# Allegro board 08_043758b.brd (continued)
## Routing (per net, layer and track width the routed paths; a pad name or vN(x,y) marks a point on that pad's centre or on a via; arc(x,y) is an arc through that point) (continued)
IO_L04_34_RX_D7: length 49.6
  TOP w0.102: v2(61.67,100.03) U4.J14 ; U5.J9 v2(36.08,102.36)
  L5_SIG w0.114: v2(61.67,100.03) 61.27,99.63 61.27,96.01 59.06,93.8 51.95,93.8 51.61,94.14 51.4,94.14 51.1,93.83 50.9,93.83 50.75,93.98 50.75,94.18 51.05,94.49 51.05,94.69 50.91,94.84 50.7,94.84 50.27,94.41 50.07,94.41 49.92,94.55 49.92,94.76 50.35,95.19 50.35,95.39 48.26,97.48 47.31,97.48 47.17,97.34 47.17,96.99 47.02,96.85 46.82,96.85 46.67,96.99 46.67,97.34 46.53,97.48 44.74,97.48 44.6,97.63 44.6,98.1 44.45,98.24 44.25,98.24 44.1,98.1 44.1,97.63 43.96,97.48 43.75,97.48 43.61,97.63 43.61,98.1 43.46,98.24 43.26,98.24 43.11,98.1 43.11,97.63 42.97,97.48 42.76,97.48 42.62,97.63 42.62,98.1 42.47,98.24 42.27,98.24 42.12,98.1 42.12,97.63 41.98,97.48 41.77,97.48 41.63,97.63 41.63,98.1 41.48,98.24 41.28,98.24 41.13,98.1 41.13,97.63 40.99,97.48 40.78,97.48 40.64,97.63 40.64,98.1 40.49,98.24 40.29,98.24 40.14,98.1 40.14,97.51 39.6,96.97 38.17,96.97 38.03,97.12 38.03,98.1 37.88,98.24 37.68,98.24 37.53,98.1 37.53,97.12 37.39,96.97 37.09,96.97 36.75,97.32 36.75,101.19 36.08,101.85 v2(36.08,102.36)
IO_L05_34_RX_D8: length 49.1
  TOP w0.102: v2(61.67,99.23) U4.J15 ; U5.K7 v2(35.28,103.16)
  L5_SIG w0.114: v2(61.67,99.23) 61.67,95.77 59.31,93.42 50.42,93.42 50.16,93.68 49.96,93.68 49.72,93.44 49.51,93.44 49.37,93.58 49.37,93.79 49.61,94.03 49.61,94.23 49.33,94.51 49.33,94.71 49.7,95.08 49.7,95.29 49.55,95.43 49.35,95.43 48.98,95.07 48.78,95.07 48.63,95.21 48.63,95.42 49,95.78 49,95.99 48.85,96.13 48.65,96.13 48.28,95.77 48.08,95.77 47.93,95.91 47.93,96.12 48.3,96.48 48.3,96.69 48.15,96.83 47.95,96.83 47.58,96.47 46.43,96.47 46.29,96.61 46.29,96.96 46.14,97.1 45.94,97.1 45.79,96.96 45.79,96.61 45.65,96.47 45.44,96.47 45.3,96.61 45.3,96.96 45.15,97.1 44.95,97.1 44.8,96.96 44.8,96.61 44.66,96.47 44.45,96.47 44.31,96.61 44.31,96.96 44.16,97.1 43.96,97.1 43.81,96.96 43.81,96.61 43.67,96.47 43.46,96.47 43.32,96.61 43.32,96.96 43.17,97.1 42.97,97.1 42.82,96.96 42.82,96.61 42.68,96.47 42.47,96.47 42.33,96.61 42.33,96.96 42.18,97.1 41.98,97.1 41.83,96.96 41.83,96.61 41.69,96.47 41.48,96.47 41.36,96.59 41.36,96.92 41.26,97.02 40.96,97.02 40.86,96.92 40.86,96.63 40.69,96.47 38.74,96.47 38.61,96.59 36.96,96.59 36.5,97.05 36.5,101 35.68,101.82 35.68,102.76 v2(35.28,103.16)
IO_L05_34_RX_D9: length 49
  TOP w0.102: v2(60.87,99.23) U4.K15 ; U5.J8 v2(36.08,103.16)
  L5_SIG w0.114: v2(60.87,99.23) 60.87,96.24 58.8,94.18 52.2,94.18 48.52,97.86 48.18,97.86 48.01,98.04 48.01,99.37 47.85,99.53 47.61,99.53 47.46,99.38 47.46,98.01 47.32,97.86 47.11,97.86 46.97,98.01 46.97,99.38 46.82,99.53 46.62,99.53 46.47,99.38 46.47,98.01 46.33,97.86 46.12,97.86 45.98,98.01 45.98,98.38 45.83,98.53 45.63,98.53 45.48,98.38 45.48,98.01 45.34,97.86 45.13,97.86 44.99,98.01 44.99,98.48 44.84,98.63 44.43,98.63 44.29,98.77 44.29,100.59 44.14,100.73 43.94,100.73 43.79,100.59 43.79,98.77 43.65,98.63 39.77,98.63 39.63,98.48 39.63,97.5 39.48,97.36 39.28,97.36 39.13,97.5 39.13,98.61 38.87,98.88 38.61,98.88 38.36,98.63 37.21,98.63 36.99,98.85 36.99,101.45 36.95,101.48 36.95,101.49 36.49,101.96 36.49,102.76 v2(36.08,103.16)
IO_L06_34_RX_D10: length 49.2
  TOP w0.102: U5.J7 v2(36.89,103.16) ; U4.H11 v2(63.27,102.43)
  L5_SIG w0.114: v2(63.27,102.43) 62.35,101.51 62.35,101.32 62.07,101.04 62.07,100.63 61.87,100.43 60.57,100.43 60.07,99.93 60.07,96.21 58.42,94.56 52.38,94.56 48.39,98.55 48.39,99.51 47.63,100.28 47.63,101.04 47.51,101.16 47.3,101.16 47.15,101.01 47.15,100.04 47,99.9 46.8,99.9 46.65,100.04 46.65,101.01 46.51,101.16 46.3,101.16 46.16,101.01 46.16,100.04 46.01,99.9 45.81,99.9 45.66,100.04 45.66,101.01 45.52,101.16 45.31,101.16 45.17,101.01 45.17,99.15 45.02,99.01 44.82,99.01 44.67,99.15 44.67,101.01 44.53,101.16 43.69,101.16 42.89,100.36 42.89,99.76 42.68,99.56 38.2,99.56 37.29,100.47 37.29,101.5 36.89,101.9 v2(36.89,103.16)
IO_L06_34_RX_D11: length 52.4
  TOP w0.102: U4.J11 v2(61.67,102.43) ; U5.H8 v2(37.69,103.16)
  L5_SIG w0.114: v2(37.69,103.16) 38.09,102.76 38.09,100.55 38.28,100.36 39.49,100.36 39.69,100.56 39.69,101.76 39.89,101.96 40.28,101.96 40.48,101.76 40.48,100.56 40.68,100.36 41.08,100.36 41.28,100.56 41.28,101.76 41.48,101.96 41.89,101.96 42.08,101.76 42.08,101.36 42.28,101.16 42.69,101.16 42.89,101.36 42.89,101.76 43.09,101.96 44.49,101.96 44.89,102.36 45.4,102.36 45.54,102.21 45.54,101.69 45.69,101.55 45.89,101.55 46.04,101.69 46.04,102.21 46.18,102.36 46.44,102.36 46.61,102.18 46.61,101.67 46.74,101.55 47.76,101.55 47.99,101.31 47.99,100.46 48.77,99.68 48.77,98.75 48.94,98.58 49.15,98.58 49.45,98.88 49.66,98.88 49.8,98.74 49.8,98.53 49.5,98.23 49.5,98.03 49.64,97.88 49.85,97.88 50.15,98.18 50.36,98.18 50.5,98.04 50.5,97.83 50.2,97.53 50.2,97.33 50.34,97.18 50.55,97.18 50.85,97.48 51.06,97.48 51.2,97.34 51.2,97.13 50.9,96.83 50.9,96.62 51.04,96.48 51.25,96.48 51.55,96.78 51.76,96.78 51.9,96.64 51.9,96.43 51.6,96.13 51.6,95.92 52.07,95.45 53.11,95.45 53.25,95.6 53.25,95.94 53.4,96.09 53.6,96.09 53.75,95.94 53.75,95.6 53.89,95.45 54.36,95.45 54.5,95.31 54.5,95.09 54.65,94.94 54.85,94.94 55,95.09 55,95.31 55.14,95.45 55.86,95.45 56.01,95.31 56.01,95.09 56.15,94.94 56.36,94.94 56.51,95.09 56.51,95.31 56.65,95.45 56.86,95.45 57,95.31 57,95.09 57.15,94.94 57.35,94.94 57.5,95.09 57.5,95.31 57.64,95.45 58.68,95.45 59.69,96.47 59.69,100.05 60.37,100.73 60.37,101.03 60.57,101.23 61.92,101.23 62.11,101.42 62.11,102.31 61.99,102.43 v2(61.67,102.43)
IO_L07_34_RX_FRAME: length 56
  TOP w0.102: v2(58.47,100.83) U4.N13 ; U5.G8 v2(38.49,103.16)
  L5_SIG w0.114: v2(38.49,103.16) 38.89,103.56 39.85,103.56 39.99,103.71 39.99,104.11 40.14,104.26 40.34,104.26 40.49,104.11 40.49,103.71 40.63,103.56 40.84,103.56 40.98,103.71 40.98,104.11 41.13,104.26 41.33,104.26 41.48,104.11 41.48,103.71 41.62,103.56 41.83,103.56 41.97,103.71 41.97,104.11 42.12,104.26 42.32,104.26 42.47,104.11 42.47,103.71 42.61,103.56 42.82,103.56 43.09,103.83 43.33,103.83 43.6,103.56 43.79,103.56 43.99,103.76 43.99,104.03 44.13,104.18 44.74,104.18 44.89,104.32 44.89,104.53 44.74,104.67 44.13,104.67 43.99,104.82 43.99,105.06 44.18,105.25 45.2,105.25 45.35,105.11 45.35,104.23 45.49,104.09 45.7,104.09 45.84,104.23 45.84,105.56 45.99,105.71 46.19,105.71 46.34,105.56 46.34,104.23 46.48,104.09 46.69,104.09 46.83,104.23 46.83,105.56 46.98,105.71 47.18,105.71 47.33,105.56 47.33,104.23 47.47,104.09 47.68,104.09 47.82,104.23 47.82,105.16 47.97,105.3 48.88,105.3 49.03,105.16 49.03,104.95 48.88,104.81 48.46,104.81 48.32,104.66 48.32,104.46 48.46,104.31 49.38,104.31 49.53,104.17 49.53,103.96 49.38,103.82 48.46,103.82 48.32,103.67 48.32,103.4 48.82,102.9 49.02,102.9 49.44,103.32 49.64,103.32 49.79,103.17 49.79,102.97 49.37,102.55 49.37,102.34 49.52,102.2 49.72,102.2 50.14,102.62 50.34,102.62 51.95,101.01 51.95,98.88 52.19,98.64 52.4,98.64 53.1,99.34 53.31,99.34 53.45,99.2 53.45,98.99 52.75,98.29 52.75,98.08 52.89,97.94 53.1,97.94 53.4,98.24 53.61,98.24 53.75,98.1 53.75,97.89 53.45,97.58 53.45,97.38 53.59,97.23 53.8,97.23 54.1,97.54 54.31,97.54 54.45,97.4 54.45,97.19 54.15,96.88 54.15,96.68 54.67,96.16 58.4,96.16 58.9,96.66 58.9,97.36 58.47,97.78 v2(58.47,100.83)
IO_L08_34_CTRL_OUT0: length 30.4
  TOP w0.102: v2(55.67,97.93) 56.63,96.96 58.51,96.96 60.47,98.92 U4.L15 ; U5.D4 v2(40.88,106.36)
  L5_SIG w0.114: v2(55.67,97.93) 55.67,99.83 55.37,100.13 54.77,100.13 54.49,100.41 54.49,100.91 51.06,104.34 51.06,105.99 49.53,107.52 44.45,107.52 43.61,108.36 41.49,108.36 41.29,108.16 41.29,106.76 v2(40.88,106.36)
IO_L08_34_CTRL_OUT1: length 31.1
  TOP w0.102: U5.E4 v2(40.08,106.36) ; v2(57.27,97.93) 57.64,97.55 58.3,97.55 59.67,98.92 U4.M15
  L5_SIG w0.114: v2(40.08,106.36) 40.49,106.76 40.49,108.96 40.69,109.17 43.69,109.17 44.96,107.9 49.66,107.9 51.44,106.12 51.44,105.36 52.16,104.63 52.16,103.73 53.87,102.03 54.27,102.03 55.37,100.93 56.77,100.93 57.27,100.43 v2(57.27,97.93)
IO_L09_34_TX_FRAME: length 28.7
  TOP w0.102: v2(38.48,102.36) U5.G9 ; v2(60.87,100.03) U4.L14
  L6_SIG w0.114: v2(38.48,102.36) 38.88,101.96 38.88,98.86 39.68,98.06 39.92,98.06 40.88,97.1 57.94,97.1 v2(60.87,100.03)
IO_L10_34_EN_AGC: length 35.1
  TOP w0.102: v2(56.47,97.93) 57.14,97.25 58.4,97.25 60,98.85 60,100.76 U4.L13 ; U5.G5 v2(37.68,105.56)
  L5_SIG w0.114: v2(37.68,105.56) 38.09,105.16 38.09,104.56 38.29,104.36 39.09,104.36 40.69,105.96 41.99,105.96 42.19,106.16 42.19,106.77 42.55,107.13 49.41,107.13 50.68,105.86 50.68,104.22 53.67,101.23 53.67,100.23 55.17,98.73 55.17,97.72 55.44,97.45 55.99,97.45 v2(56.47,97.93)
IO_L11_34_ENABLE: length 30.7
  TOP w0.102: U5.G6 v2(37.68,104.76) ; U4.K12 v2(60.87,101.63)
  L6_SIG w0.114: v2(37.68,104.76) 38.09,105.16 38.09,105.76 38.29,105.96 38.69,105.96 39.69,106.96 39.69,107.36 39.89,107.56 51.94,107.56 54.07,105.43 55.17,105.43 55.77,104.83 56.17,104.83 56.37,105.03 56.37,105.43 56.66,105.73 57.37,105.73 57.87,105.23 58.67,105.23 59.67,104.23 59.67,102.23 59.87,102.03 60.47,102.03 v2(60.87,101.63)
IO_L11_34_TXNRX: length 32.7
  TOP w0.102: U5.H4 v2(36.89,106.36) ; U4.K11 v2(60.87,102.43)
  L6_SIG w0.114: v2(60.87,102.43) 60.47,102.83 60.47,105.83 60.27,106.03 54.47,106.03 50.7,109.8 38.02,109.8 37.29,109.06 37.29,106.76 v2(36.89,106.36)
IO_L12_MRCC_34_DATA_CLK: length 55.5
  TOP w0.102: U5.G11 v2(38.49,100.76) ; U4.L12 v2(60.07,101.63)
  L5_SIG w0.114: v2(60.07,101.63) 60.07,100.93 59.31,100.17 59.31,96.57 58.57,95.83 54.49,95.83 53.09,97.23 52.88,97.23 52.45,96.8 52.25,96.8 52.1,96.95 52.1,97.15 52.53,97.58 52.53,97.79 52.39,97.93 52.18,97.93 51.75,97.5 51.55,97.5 51.4,97.65 51.4,97.85 51.83,98.28 51.83,98.49 51.69,98.63 51.48,98.63 51.05,98.2 50.85,98.2 50.7,98.35 50.7,98.55 51.51,99.36 51.51,99.57 51.37,99.71 51.16,99.71 50.35,98.9 50.15,98.9 50,99.05 50,99.25 50.94,100.19 50.94,100.4 50.79,100.54 50.59,100.54 49.52,99.48 49.32,99.48 49.17,99.62 49.17,99.83 50.62,101.27 50.62,101.48 50.43,101.67 50.22,101.67 48.86,100.3 48.65,100.3 48.51,100.44 48.51,100.65 49.28,101.42 49.28,101.8 49.04,102.04 48.83,102.04 48.47,101.68 48.26,101.68 48.12,101.82 48.12,102.03 48.48,102.39 48.48,102.6 48.34,102.74 48.13,102.74 47.51,102.12 47.31,102.12 47.16,102.27 47.16,102.47 47.78,103.09 47.78,103.42 47.5,103.71 46.99,103.71 46.85,103.56 46.85,102.9 46.7,102.76 46.46,102.76 46.32,102.9 46.32,103.56 46.17,103.71 45.97,103.71 45.82,103.56 45.82,102.9 45.68,102.76 45.47,102.76 45.33,102.9 45.33,103.56 45.18,103.71 44.97,103.71 44.83,103.56 44.83,102.78 44.68,102.63 44.48,102.63 44.33,102.78 44.33,103.05 44.19,103.2 43.98,103.2 43.84,103.05 43.84,102.9 43.69,102.76 39.09,102.76 38.89,102.57 38.89,101.17 v2(38.49,100.76)
IO_L13_34_CTRL_OUT2: length 29.4
  TOP w0.102: U5.E5 v2(39.28,105.56) ; U4.N11 v2(58.47,102.43)
  L5_SIG w0.114: v2(58.47,102.43) 57.17,102.43 56.37,101.62 55.67,101.62 54.67,102.63 54.67,102.93 53.47,104.13 53.47,104.73 53.06,105.13 52.76,105.13 52.07,105.82 52.07,106.5 49.95,108.63 45.25,108.63 43.95,109.93 40.52,109.93 39.75,109.17 39.75,108.63 39.48,108.36 38.98,108.36 38.79,108.16 38.79,107.06 39.28,106.56 v2(39.28,105.56)
IO_L13_34_CTRL_OUT3: length 30.3
  TOP w0.102: U5.E6 v2(40.08,104.76) ; U4.N12 v2(58.47,101.63)
  L5_SIG w0.114: v2(40.08,104.76) 40.48,105.16 42.09,105.16 42.59,105.66 42.59,106.41 42.93,106.75 48.14,106.75 49.91,104.98 49.91,103.98 50.36,103.53 50.86,103.53 53.37,101.03 53.37,99.98 54.77,98.58 54.77,97.62 55.32,97.07 57.12,97.07 57.67,97.62 57.67,100.83 v2(58.47,101.63)
IO_L15_34_TX_D0: length 23.4
  TOP w0.102: U4.P15 58.07,99.33 57.69,98.95 54.05,98.95 v2(53.85,98.75) ; U5.E12 39.76,99.48 39.76,99.46 v2(40.07,99.15)
  L6_SIG w0.114: v2(53.85,98.75) 54.49,98.75 54.74,98.5 54.74,98.24 54.36,97.86 52.03,97.86 51.77,98.12 51.32,98.12 51.06,97.86 50.69,97.86 50.43,98.12 49.98,98.12 49.73,97.86 49.36,97.86 49.1,98.12 48.65,98.12 48.39,97.86 48.02,97.86 47.76,98.12 47.31,98.12 47.06,97.86 46.68,97.86 46.42,98.12 45.97,98.12 45.72,97.86 45.34,97.86 45.09,98.12 44.64,98.12 44.38,97.86 40.98,97.86 40.07,98.77 v2(40.07,99.15)
IO_L15_34_TX_D1: length 23.2
  TOP w0.102: v2(54.07,100.63) 54.46,101.03 56.77,101.03 56.97,101.22 57.26,101.22 U4.R13 ; U5.D11 v2(40.89,99.96)
  L6_SIG w0.114: v2(54.07,100.63) 53.37,100.63 52.97,100.23 52.97,99.64 52.58,99.26 50.51,99.26 50.37,99.41 50.37,100 50.22,100.15 50.01,100.15 49.87,100 49.87,99.41 49.72,99.26 49.52,99.26 49.37,99.41 49.37,100 49.23,100.15 49.02,100.15 48.88,100 48.88,99.41 48.73,99.26 48.53,99.26 48.38,99.41 48.38,100 48.24,100.15 48.03,100.15 47.89,100 47.89,99.41 47.74,99.26 46.99,99.26 46.23,100.02 43.95,100.02 43.48,99.56 41.49,99.56 41.28,99.76 41.28,99.89 41.21,99.96 v2(40.89,99.96)
IO_L16_34_TX_D2: length 22.7
  TOP w0.102: U5.E11 40.07,99.97 40.07,99.96 v2(40.08,99.95) ; v2(54.97,99.63) U4.R15
  L6_SIG w0.114: v2(40.08,99.95) 40.08,99.66 40.18,99.56 40.28,99.56 40.48,99.36 40.48,98.86 41.1,98.24 44.2,98.24 44.43,98.48 44.43,99.01 44.58,99.16 44.78,99.16 44.93,99.01 44.93,98.7 45.13,98.5 52.96,98.5 53.95,99.49 54.31,99.49 54.72,99.07 55.61,99.07 55.81,99.27 55.81,99.45 55.63,99.63 v2(54.97,99.63)
IO_L16_34_TX_D3: length 23.6
  TOP w0.102: U5.D10 v2(40.88,100.76) ; v2(51.36,100.63) 52.36,101.63 56.27,101.63 57.07,102.43 57.66,102.43 U4.P11
  L6_SIG w0.114: v2(51.36,100.63) 51.79,100.63 51.95,100.78 51.95,101.04 51.82,101.17 50.03,101.17 49.8,100.93 49.59,100.93 49.45,101.07 49.45,101.32 49.3,101.46 49.1,101.46 48.95,101.32 48.95,101.07 48.81,100.93 48.6,100.93 48.46,101.07 48.46,101.32 48.31,101.46 48.11,101.46 47.96,101.32 47.96,101.07 47.82,100.93 47.61,100.93 47.47,101.07 47.47,101.32 47.32,101.46 47.12,101.46 46.97,101.32 46.97,100.95 46.83,100.8 46.62,100.8 46.48,100.95 46.48,101.32 46.33,101.46 46.09,101.46 45.49,100.86 44.49,100.86 44.19,101.16 41.28,101.16 v2(40.88,100.76)
IO_L17_34_TX_D4: length 23.2
  TOP w0.102: U4.R11 56.87,102.83 v2(56.07,102.03) ; U5.E10 v2(40.08,100.76)
  L6_SIG w0.114: v2(56.07,102.03) 56.5,101.6 56.5,101.16 55.5,100.16 53.61,100.16 53.39,99.95 53.39,99.44 52.84,98.88 46.77,98.88 46.13,99.51 44.24,99.51 43.95,99.22 43.95,98.92 43.69,98.66 41.49,98.66 41.28,98.86 41.28,99.36 41.09,99.56 40.69,99.56 40.48,99.76 40.48,100.16 40.28,100.36 40.16,100.36 40.08,100.43 v2(40.08,100.76)
IO_L17_34_TX_D5: length 22.7
  TOP w0.102: U5.D9 v2(40.88,101.56) ; v2(52.37,100.63) 53.06,101.33 56.54,101.33 56.67,101.45 56.69,101.45 U4.R12
  L6_SIG w0.114: v2(40.88,101.56) 41.29,101.96 43.89,101.96 44.59,101.26 45.29,101.26 45.89,101.86 49.6,101.86 49.91,101.55 52.14,101.55 52.47,101.88 52.47,102.19 52.62,102.33 53.47,102.33 53.85,101.94 53.85,101.62 52.86,100.63 v2(52.37,100.63)
IO_L18_34_TX_D6: length 22.9
  TOP w0.102: v2(52.37,99.83) 52.94,99.25 57.49,99.25 57.67,99.43 57.67,100.03 U4.P14 ; U5.E9 v2(40.08,101.56)
  L6_SIG w0.114: v2(52.37,99.83) 51.75,99.83 51.57,99.64 51.06,99.64 50.8,99.9 50.8,100.55 50.59,100.76 50.27,100.76 50.04,100.53 47.63,100.53 47.41,100.31 47.41,99.89 47.29,99.76 47.02,99.76 46.89,99.89 46.89,100.26 46.75,100.4 43.74,100.4 43.39,100.76 43.14,100.76 43,100.61 43,100.5 42.85,100.36 40.73,100.36 40.48,100.6 40.48,101.16 v2(40.08,101.56)
IO_L18_34_TX_D7: length 22.7
  TOP w0.102: U4.P13 57.66,100.82 56.96,100.82 56.77,100.63 55.17,100.63 55.17,100.63 v2(54.96,100.63) ; U5.D8 v2(40.88,102.36)
  L6_SIG w0.114: v2(40.88,102.36) 41.29,102.76 43.69,102.76 44.19,102.26 49.85,102.26 50,102.4 50,102.62 50.14,102.76 50.48,102.76 50.62,102.62 50.62,102.4 50.77,102.26 50.97,102.26 51.12,102.4 51.12,102.62 51.26,102.76 53.59,102.76 54.3,102.05 54.87,102.05 55.14,102.33 55.47,102.33 55.67,102.13 55.67,100.83 55.46,100.63 v2(54.96,100.63)
IO_L19_34_TX_D8: length 22.6
  TOP w0.102: U5.E8 v2(40.08,102.36) ; v2(55.96,103.63) 56.36,104.03 58.47,104.03 U4.N9
  L6_SIG w0.114: v2(55.96,103.63) 53.47,103.63 53.4,103.56 47.39,103.56 47.25,103.71 46.23,103.71 45.99,103.46 45.99,103.21 45.85,103.06 45.64,103.06 45.5,103.21 45.5,103.52 45.35,103.66 45.14,103.66 45,103.52 45,103.21 44.85,103.06 44.65,103.06 44.5,103.21 44.5,103.65 44.29,103.86 40.99,103.86 40.48,103.36 40.48,102.76 v2(40.08,102.36)
IO_L19_34_TX_D9: length 23.4
  TOP w0.102: U4.M9 59.27,104.83 v2(58.47,104.83) ; U5.D7 v2(40.88,103.16)
  L6_SIG w0.114: v2(58.47,104.83) 58.47,104.43 58.07,104.03 56.57,104.03 56.37,103.83 56.37,103.43 56.17,103.24 53.97,103.24 53.9,103.16 49.89,103.16 49.39,102.66 49.08,102.66 48.93,102.81 48.93,103.02 48.79,103.16 48.58,103.16 48.44,103.02 48.44,102.81 48.29,102.66 48.09,102.66 47.94,102.81 47.94,103.02 47.8,103.16 47.59,103.16 47.45,103.02 47.45,102.81 47.3,102.66 47.1,102.66 46.95,102.81 46.95,103.02 46.81,103.16 46.6,103.16 46.46,103.02 46.46,102.81 46.31,102.66 44.39,102.66 43.49,103.56 41.29,103.56 40.89,103.16 v2(40.88,103.16)
IO_L20_34_TX_D10: length 22.4
  TOP w0.102: v2(56.76,105.22) 56.77,105.23 U4.R8 ; U5.F8 v2(39.28,102.36)
  L6_SIG w0.114: v2(56.76,105.22) 56.67,104.93 56.37,104.63 56.37,104.23 56.16,104.03 53.91,104.03 53.6,104.34 53.6,104.9 53.39,105.1 44.58,105.1 44.1,105.59 42.71,105.59 42.48,105.36 42.48,104.91 41.93,104.36 40.68,104.36 40.22,103.9 40.02,103.9 39.68,103.56 39.68,102.76 39.29,102.36 v2(39.28,102.36)
IO_L20_34_TX_D11: length 22.8
  TOP w0.102: U4.R7 56.86,106.03 56.77,105.93 54.57,105.93 v2(53.07,104.43) ; U5.E7 v2(40.08,103.16)
  L6_SIG w0.114: v2(40.08,103.16) 40.08,103.56 40.19,103.66 40.39,103.66 40.85,104.12 42.33,104.12 42.94,104.73 44.06,104.73 44.68,104.12 45.26,104.12 45.41,104.26 45.41,104.42 45.55,104.56 45.76,104.56 45.9,104.42 45.9,104.26 46.05,104.12 46.25,104.12 46.4,104.26 46.4,104.42 46.54,104.56 46.75,104.56 46.89,104.42 46.89,104.26 47.04,104.12 47.24,104.12 47.39,104.26 47.39,104.42 47.53,104.56 47.74,104.56 47.88,104.42 47.88,104.14 48.03,103.99 48.23,103.99 48.38,104.14 48.38,104.54 48.52,104.69 48.73,104.69 48.87,104.54 48.87,104.12 49.03,103.96 52.94,103.96 53.07,104.09 v2(53.07,104.43)
IO_L21_34_CTRL_OUT4: length 32.1
  TOP w0.102: U4.M10 v2(59.27,103.23) ; U5.F6 v2(38.49,104.76)
  L5_SIG w0.114: v2(59.27,103.23) 59.67,102.83 59.67,102.22 59.47,102.02 57.47,102.02 56.8,101.36 55.45,101.36 54.47,102.33 54.07,102.33 52.56,103.83 52.56,104.73 51.8,105.49 51.8,106.26 49.81,108.26 45.11,108.26 43.82,109.55 40.64,109.55 40.14,109.04 40.14,108.61 39.68,108.16 39.68,105.36 39.49,105.16 38.89,105.16 v2(38.49,104.76)
IO_L21_34_CTRL_OUT5: length 30.6
  TOP w0.102: U5.F5 v2(38.49,105.55) ; U4.M11 v2(59.27,102.43)
  L5_SIG w0.114: v2(59.27,102.43) 58.87,102.83 56.88,102.83 56.47,102.43 55.9,102.43 55.57,102.76 55.57,103.03 54.87,103.73 54.23,103.73 53.77,104.19 53.77,105.63 49.09,110.31 40.26,110.31 38.49,108.53 38.49,106.96 38.88,106.56 38.88,105.95 v2(38.49,105.55)
IO_L22_34_CTRL_OUT6: length 32.3
  TOP w0.102: U5.F4 v2(38.48,106.36) ; v2(58.47,106.43) U4.N7
  L5_SIG w0.114: v2(58.47,106.43) 57.3,105.26 57.3,104.36 56.97,104.03 55.8,104.03 55.57,104.26 55.57,104.83 49.33,111.07 39.88,111.07 38.23,109.42 37.72,109.42 37.28,108.98 37.28,106.06 37.38,105.96 38.08,105.96 v2(38.48,106.36)
IO_L22_34_CTRL_OUT7: length 30.1
  TOP w0.102: v2(58.47,105.63) U4.N8 ; U5.G4 v2(37.68,106.36)
  L5_SIG w0.114: v2(37.68,106.36) 38.09,106.76 38.09,108.64 40.14,110.69 49.21,110.69 54.77,105.13 54.77,104.23 55.77,103.23 57.27,103.23 58.07,104.03 58.07,105.23 v2(58.47,105.63)
IO_L23_35_SPI_CLK: length 70.5
  TOP w0.102: U5.J5 v2(36.09,105.56) ; U4.E11 v2(65.67,102.43)
  L5_SIG w0.114: v2(65.67,102.43) 66.07,102.83 67.47,102.83 67.67,102.62 67.67,100.13 67.87,99.93 67.87,98.33 67.37,97.83 67.37,90.3 66.46,89.39 63.01,89.39 62.72,89.1 51.31,89.1 50.68,88.47 43.82,88.47 43.06,89.23 36.71,89.23 30.45,95.49 30.45,102.5 33.1,105.16 35.69,105.16 v2(36.09,105.56)
IO_L23_35_SPI_ENB: length 66.4
  TOP w0.102: U5.K6 v2(35.28,104.76) ; U4.E12 v2(65.67,101.63)
  L5_SIG w0.114: v2(65.67,101.63) 66.07,102.03 66.67,102.03 66.87,101.83 66.87,100.32 67.57,99.62 67.57,98.53 67.07,98.03 67.07,90.64 66.21,89.77 62.63,89.77 62.34,89.48 51.06,89.48 50.42,88.85 46.1,88.85 45.47,89.48 36.96,89.48 30.75,95.7 30.75,102.38 32.72,104.36 34.88,104.36 v2(35.28,104.76)
IO_L24_35_SPI_DI: length 64.2
  TOP w0.102: U5.J4 v2(36.08,106.36) ; U4.E13 v2(65.67,100.83)
  L5_SIG w0.114: v2(65.67,100.83) 65.77,100.53 66.47,99.82 66.47,91.21 65.8,90.53 62.12,90.53 61.83,90.24 37.21,90.24 31.34,96.12 31.34,102.12 31.53,102.32 31.74,102.32 31.96,102.09 32.17,102.09 32.31,102.23 32.31,102.44 32.09,102.67 32.09,102.87 32.77,103.56 35.78,103.56 36.48,104.26 U5.J4 v2(36.08,106.36)
IO_L24_35_SPI_DO: length 62.7
  TOP w0.102: U4.F12 v2(64.87,101.63) ; U5.L6 v2(34.48,103.96)
  L5_SIG w0.114: v2(34.48,103.96) 32.75,103.96 31.05,102.25 31.05,95.9 37.09,89.86 62.08,89.86 62.37,90.15 66.08,90.15 66.77,90.85 66.77,98.23 67.27,98.73 67.27,99.42 66.07,100.63 66.07,101.13 65.97,101.23 65.53,101.23 65.13,101.63 v2(64.87,101.63)
JTAG_TCK: length 49.9
  TOP w0.102: P1.4 71.38,80.59 68.84,80.59 TCK.1 ; v1(78.88,103.71) 78.37,104.21 72.59,104.21 72.08,104.72 70.09,104.72 69.98,104.83 64.07,104.83 U4.G9
  L5_SIG w0.114: v1(75.7,83) 75.7,83.64 77.36,85.3 77.36,91.02 78.25,91.91 78.25,97.45 77.28,98.42 77.28,100.15 78.25,101.12 78.25,103.07 v1(78.88,103.71)
  BOTTOM w0.102: v1(75.7,83) 75.06,82.37 73.28,82.37 72.65,81.73 P1.4
JTAG_TDI: length 43.7
  TOP w0.102: U4.L7 v2(60.07,106.43) ; P1.8 75.95,80.08 77.6,80.08 78.36,79.32 78.36,78.69 TDI.1
  L5_SIG w0.114: v2(60.07,106.43) 60.07,106.43 60.46,106.03 62.67,106.03 63.97,104.73 67.81,104.73 69.98,102.57 69.98,95.71 71.12,94.56 71.12,89.74 72.39,88.47 72.39,82.12 P1.8
JTAG_TDO: length 42.9
  TOP w0.102: P1.6 75.19,80.59 77.73,80.59 78.36,79.96 TDO.1 ; U4.L8 v2(60.07,105.63)
  L5_SIG w0.114: P1.6 71.89,81.35 71.89,88.34 70.74,89.48 70.74,94.31 69.22,95.83 69.22,100.92 68.77,101.37 68.77,101.85 68.47,102.15 68.47,103.63 67.68,104.43 63.87,104.43 63.07,105.23 60.46,105.23 60.07,105.63 v2(60.07,105.63)
JTAG_TMS: length 38.5
  TOP w0.102: TMS.1 70.11,79.32 P1.2 ; U4.L9 v2(60.07,104.83)
  L5_SIG w0.114: v2(60.07,104.83) 61.27,103.63 67.67,103.63 68.07,103.23 68.07,102.19 68.46,101.81 68.46,101.1 68.84,100.72 68.84,95.58 70.36,94.05 70.36,89.23 71.38,88.21 P1.2
PG_1P0V: length 21.6
  TOP w0.305: U3.16 101.11,93.43 v1(101.48,93.8)
  BOTTOM w0.203: R86.1 97.67,110.18 98.3,109.55 98.3,106.3 102.24,102.36 102.24,94.56 v1(101.48,93.8)
  BOTTOM w0.305: R6.2 v1(101.48,93.8)
PG_1P3V: length 94.8
  TOP w0.127: U1.5 30.82,82.79 30.99,82.62 v1(30.99,82.24) ; v2(67.27,104.03) 66.87,104.43 U4.C9 ; U7.5 v1(51.69,82.12) ; U12.4 v1(59.82,86.29)
  L5_SIG w0.127: v1(79.01,83.04) 79.01,97.52 79.78,98.29 79.78,100.02 79.01,100.79 79.01,101.33 80.03,102.35 v1(80.03,102.73)
  L6_SIG w0.127: v1(79.01,83.04) 78.12,82.15 72.28,82.15 67.45,86.98 64.41,86.98 63.72,86.29 v1(59.82,86.29) ; v1(80.03,102.73) 80.03,103.68 79.49,104.21 78.49,104.21 78.3,104.03 v2(67.27,104.03)
  BOTTOM w0.127: v1(59.82,86.29) 56.53,83 55.88,83 PG_1P3V.1 54.99,82.12 v1(51.69,82.12) 46.36,82.12 45.22,80.97 38.54,80.97 37.74,81.77 31.46,81.77 v1(30.99,82.24) ; R13.2 81.49,103.9 C47.1 80.06,103.9 R15.1 80.03,103.32 v1(80.03,102.73)
PG_1P8V: length 12
  TOP w0.203: v2(100.33,119.38) 100.33,119.33 100.34,119.32 U6.13 ; v2(100.96,112.58) 100.84,112.93 U6.29
  L5_SIG w0.305: v2(100.33,119.38) 100.33,119.33 100.84,118.82 102.11,118.82 102.75,118.18 102.75,114.75 100.96,112.96 v2(100.96,112.58)
  BOTTOM w0.305: v2(100.96,112.58) 100.96,111.83 R59.1
PG_1P35V: length 124.9
  TOP w0.127: U7.4 50.76,81.52 51.06,81.23 v1(52.58,81.23) ; v1(30.23,81.23) 29.59,81.87 U1.4
  TOP w0.203: v2(100.97,120.09) 100.84,119.7 U6.12
  L5_SIG w0.127: v2(100.97,120.09) 97.01,120.09 94.12,117.2 94.12,110.47 88.41,104.76 88.41,99.68 87.9,99.17 87.9,93.07 86.25,91.42 86.25,90.15 84.73,88.63 84.73,83.75 v1(85.47,83)
  L6_SIG w0.127: v1(52.58,81.23) 52.58,81.99 53.51,82.91 56.53,82.91 59.2,85.58 65.17,85.58 65.68,86.09 67.58,86.09 72.03,81.64 78.78,81.64 80.52,83.39 85.09,83.39 v1(85.47,83)
  BOTTOM w0.127: v1(30.23,81.23) 37.27,81.23 38.24,80.25 45.74,80.25 46.72,81.23 v1(52.58,81.23) ; v2(100.97,120.09) 100.97,119.33 100.46,118.82 93.98,118.82 92.08,116.91 R50.1
PL_GPIO0: length 50.1
  TOP w0.127: U4.K13 v2(60.87,100.83)
  L6_SIG w0.127: v2(60.87,100.83) 61.07,100.83 61.47,101.23 61.97,101.23 62.77,102.03 65.07,102.03 65.27,101.83 65.27,101.43 65.47,101.23 65.87,101.23 66.07,101.03 66.07,99.92 66.37,99.62 66.37,98.72 67.07,98.02 67.07,90.62 73.56,84.13 90.06,84.13 91.7,82.5 91.7,79.96 L10P.1
PL_GPIO1: length 55.5
  TOP w0.102: U4.M12 v2(59.27,101.63)
  L6_SIG w0.127: L12N.1 94.24,79.96 94.24,81.86 91.19,84.91 77.35,84.91 76.27,85.99 72.9,85.99 67.87,91.02 67.87,99.22 66.87,100.22 66.87,101.03 66.67,101.23 66.27,101.23 66.07,101.43 66.07,102.63 65.87,102.83 61.47,102.83 61.27,102.63 61.27,101.43 61.07,101.23 59.57,101.23 59.27,101.53 v2(59.27,101.63)
PL_GPIO2: length 52
  TOP w0.127: U4.R10 v2(56.79,103.63)
  L6_SIG w0.127: v2(56.79,103.63) 56.79,103.41 58.07,102.13 58.07,100.7 58.33,100.43 62.61,100.43 62.89,100.71 62.89,101.05 63.07,101.23 65.07,101.23 65.27,101.03 65.27,99.72 65.47,99.52 65.87,99.52 66.07,99.32 66.07,98.2 66.67,97.6 66.67,90.42 73.36,83.73 89.83,83.73 90.43,83.13 L24N.1
PS-SRST#: length 33.3
  TOP w0.127: v1(79.78,101.03) 78.58,101.03 78.38,100.83 72.77,100.83 72.28,101.32 R74.2 70.49,102.18 70.24,102.43 68.07,102.43 U4.B11 ; v2(84.08,116.26) U13.A4
  L5_SIG w0.127: v1(79.78,101.03) 80.78,102.03 81.98,102.03 84.08,104.12 v2(84.08,116.26)
PS_GPIO0: length 54.7
  TOP w0.102: U4.D8 v2(65.67,105.63)
  L5_SIG w0.127: v2(65.67,105.63) 66.07,106.03 66.67,106.03 67.17,106.53 67.77,106.53 68.57,107.33 71.27,107.33 v1(72.07,108.13)
  L6_SIG w0.127: MIO0.1 100.59,82.75 92.89,90.45 92.89,94.32 v1(92.49,94.72)
  BOTTOM w0.127: v1(92.49,94.72) 92.49,95.29 92.35,95.44 92.35,98.66 91.46,99.55 90.31,99.55 89.68,100.19 89.68,102.22 85.29,106.61 75.52,106.61 75.3,106.83 72.57,106.83 72.07,107.33 v1(72.07,108.13)
PS_GPIO1: length 55.8
  TOP w0.127: U4.B10 68.07,103.23 71.77,103.23 72.17,102.83 77.13,102.83 78.38,101.58 80.32,101.58 v1(80.88,101.03)
  L5_SIG w0.127: v1(80.88,101.03) 81.98,99.92 81.98,99.02 80.98,98.02 80.98,85.39 84.73,81.64 87.98,81.64 89.16,80.46 89.16,77.92 89.79,77.29 99.19,77.29 MIO10.1
PS_GPIO2: length 52.9
  TOP w0.127: U4.D6 v2(65.67,106.43)
  L5_SIG w0.127: v2(65.67,106.43) 66.07,106.83 67.47,106.83 68.27,107.63 70.77,107.63 v1(71.27,108.13)
  L6_SIG w0.127: MIO11.1 98.05,84.65 91.89,90.81 v1(91.89,94.12)
  BOTTOM w0.127: v1(71.27,108.13) 71.27,107.63 72.37,106.53 75.18,106.53 75.39,106.31 85.08,106.31 89.3,102.09 89.3,99.93 90.19,99.04 91.33,99.04 91.89,98.48 v1(91.89,94.12)
PS_GPIO3: length 51.1
  TOP w0.127: v1(70.27,108.13) 69.57,108.13 69.47,108.03 68.07,108.03 U4.B5
  L6_SIG w0.127: v1(90.69,94.12) 90.69,91.38 96.78,85.29 96.78,79.96 MIO09.1
  BOTTOM w0.127: v1(70.27,108.13) 72.17,106.23 75.08,106.23 75.28,106.03 84.85,106.03 88.92,101.96 88.92,99.68 90.69,97.91 v1(90.69,94.12)
PS_GPIO4: length 43.3
  TOP w0.127: U4.C13 v2(67.27,100.83)
  L6_SIG w0.127: MIO53.1 95.51,83.51 93.73,85.29 77.51,85.29 75.29,87.52 71.97,87.52 69.47,90.02 69.47,98.12 67.27,100.33 v2(67.27,100.83)
PS_GPIO5: length 45.8
  TOP w0.127: U4.D13 v2(66.47,100.83)
  L5_SIG w0.127: MIO49.1 94.24,79.96 92.21,79.96 91.7,80.46 v1(91.7,83.39)
  L6_SIG w0.127: v1(91.7,83.39) 90.55,84.53 77.22,84.53 76.16,85.59 72.7,85.59 67.47,90.82 67.47,99.12 66.47,100.13 v2(66.47,100.83)
PS_GPIO6: length 47
  TOP w0.127: v2(68.08,101.62) U4.B12
  L5_SIG w0.127: v1(96.14,82.88) 94.62,82.88 MIO48.1
  L6_SIG w0.127: v1(96.14,82.88) 96.14,84.27 94.75,85.67 77.73,85.67 75.49,87.92 72.17,87.92 69.87,90.22 69.87,98.22 67.67,100.42 67.67,101.22 v2(68.08,101.62)
PS_MIO01_500_QSPI0_SS_B: length 38.3
  TOP w0.127: v1(76.89,114.43) 76.89,113.85 74.43,111.38 74.43,108.78 73.68,108.03 73.08,108.03 72.67,107.63 U4.A5 ; U13.C2 v2(81.15,120.19)
  L5_SIG w0.127: v2(81.15,120.19) 81.48,120.53 81.48,122.04 81.28,122.24 80.88,122.24 80.67,122.03 80.67,120.62 80.52,120.47 80.31,120.47 80.16,120.62 80.16,122.27 80.01,122.42 79.8,122.42 79.65,122.27 79.65,120.87 79.51,120.72 79.3,120.72 79.15,120.87 79.15,122.27 79,122.42 78.79,122.42 78.64,122.27 78.64,120.87 78.49,120.72 78.28,120.72 78.13,120.87 78.13,121.97 77.98,122.12 77.56,122.12 77.35,121.91 77.35,114.88 v1(76.89,114.43)
  BOTTOM w0.127: v2(81.15,120.19) 81.63,119.71 81.93,119.71 R14.2
PS_MIO02_500_QSPI0_IO0: length 33.8
  TOP w0.127: U13.D3 v2(79.15,119.19) ; U4.A8 69.97,105.23 70.1,105.1 72.27,105.1 72.39,105.23 78.25,105.23 79.01,104.47 81.66,104.47 v1(82.68,105.48)
  L5_SIG w0.127: v1(82.68,105.48) 82.68,111.96 82.38,112.26 82.38,112.47 82.55,112.64 82.55,112.85 82.4,113 82.19,113 82.02,112.83 81.81,112.83 81.58,113.06 81.58,113.27 81.81,113.51 81.81,113.72 81.67,113.87 81.45,113.87 81.22,113.63 81.01,113.63 80.78,113.86 80.78,118.18 79.77,119.19 v2(79.15,119.19)
  BOTTOM w0.127: R120.1 78.47,119.19 v2(79.15,119.19)
PS_MIO03_500_QSPI0_IO1: length 37.5
  TOP w0.127: U13.D2 v2(79.15,120.19) ; U4.A7 68.9,105.6 v2(70.19,105.6)
  L5_SIG w0.127: v2(70.19,105.6) 70.19,106.2 70.49,106.5 71.63,106.5 72.59,107.45 72.8,107.45 73.41,106.84 73.62,106.84 73.77,106.99 73.77,107.2 73.15,107.81 73.15,108.02 73.3,108.17 73.51,108.17 74.43,107.26 74.64,107.26 74.79,107.4 74.79,107.62 73.87,108.53 73.87,108.74 74.02,108.89 74.23,108.89 74.85,108.27 75.06,108.27 75.21,108.42 75.21,108.63 74.59,109.25 74.59,109.46 74.74,109.61 74.95,109.61 76.2,108.36 76.41,108.36 76.56,108.51 76.56,108.72 75.31,109.97 75.31,110.43 75.81,110.94 77.48,110.94 77.73,111.18 77.73,112.99 77.58,113.14 76.86,113.14 76.71,113.29 76.71,113.5 76.86,113.65 77.58,113.65 77.73,113.8 77.73,118.66 77.88,118.81 78.34,118.81 78.49,118.96 78.49,119.17 78.34,119.32 77.88,119.32 77.73,119.47 77.73,119.83 78.08,120.19 v2(79.15,120.19)
  BOTTOM w0.127: v2(79.15,120.19) 78.45,120.19 R119.1
PS_MIO04_500_QSPI0_IO2: length 36
  TOP w0.127: U4.C8 v2(66.47,105.63) ; U13.C4 v2(80.13,117.18)
  L5_SIG w0.127: v2(80.13,117.18) 79.51,117.8 79,117.8 78.11,116.91 78.11,114.25 78.62,113.74 78.62,109.55 78.2,109.13 78.2,108.92 79.07,108.05 79.07,107.84 78.92,107.69 78.71,107.69 77.84,108.56 77.63,108.56 77.45,108.38 77.45,108.17 78.13,107.49 78.13,107.28 77.98,107.13 77.77,107.13 77.09,107.81 76.88,107.81 76.73,107.66 76.73,107.45 77.41,106.77 77.41,106.56 77.26,106.41 77.05,106.41 76.37,107.09 76.16,107.09 76.01,106.94 76.01,106.73 76.69,106.05 76.69,105.84 76.54,105.69 76.33,105.69 75.65,106.37 72.12,106.37 70.85,105.1 69.85,105.1 68.93,106.03 67.07,106.03 66.77,105.73 v2(66.47,105.63)
  BOTTOM w0.127: R121.1 80.14,117.17 v2(80.13,117.18)
PS_MIO05_500_QSPI0_IO3: length 73.5
  TOP w0.127: U4.A9 71.97,104.43 72.47,103.93 77.77,103.93 v1(78.88,102.82) ; P1.5 73.92,76.15 75.19,74.88 JTAG_BOOT.1 ; U13.D4 v2(79.15,117.19)
  L5_SIG w0.127: P1.5 73.92,77.16 74.43,76.65 77.09,76.65 77.85,77.42 77.85,90.62 78.63,91.4 78.63,97.77 79.38,98.52 79.38,99.92 78.63,100.67 78.63,101.96 78.88,102.22 v1(78.88,102.82) 80,103.93 81.08,103.93 82.17,105.02 82.17,110.31 81.58,110.9 81.58,111.11 82.07,111.6 82.07,111.81 81.92,111.96 81.71,111.96 81.22,111.47 81.01,111.47 80.83,111.65 80.83,111.86 81.26,112.28 81.26,112.49 81.11,112.64 80.9,112.64 80.47,112.22 80.26,112.22 80.11,112.37 80.11,112.58 80.54,113 80.54,113.21 80.39,113.36 80.18,113.36 79.76,112.94 79.55,112.94 79.4,113.09 79.4,113.3 79.82,113.72 79.82,113.93 79.67,114.08 78.91,114.08 78.49,114.5 78.49,116.53 v2(79.15,117.19)
  BOTTOM w0.127: v2(79.15,117.19) 79.15,116.42 R122.1
PS_MIO06_500_QSPI0_SCLK: length 34.6
  TOP w0.127: U13.B2 v2(82.15,120.19) ; v1(80.92,102.73) 80.12,101.93 78.54,101.93 77.34,103.13 72.27,103.13 71.77,103.63 U4.A10
  L5_SIG w0.127: v2(82.15,120.19) 81.28,119.33 81.28,115.01 83.19,113.1 83.19,105 v1(80.92,102.73)
  BOTTOM w0.127: v2(82.15,120.19) 82.15,120.97 R116.1
PS_MIO07_500_USB_RESET_B: length 22.2
  TOP w0.127: v2(69.58,101.86) 68.64,101.86 U4.A12 ; U15.27 85.84,101.43 v1(84.59,102.69)
  L6_SIG w0.127: v2(69.58,101.86) 69.84,102.12 76.68,102.12 76.88,101.93 77.98,101.93 79.38,100.53 81.18,100.53 81.78,101.13 81.78,101.81 82.66,102.69 v1(84.59,102.69)
  BOTTOM w0.127: R76.2 69.58,101.52 v2(69.58,101.86)
PS_MIO28_501_USB0_D4: length 23.7
  TOP w0.102: U4.A15 69.1,99.63 69.98,98.75 72.65,98.75 74.68,96.72 74.93,96.72 v1(75.19,96.47) ; v1(81.79,96.36) U15.7
  L6_SIG w0.114: v1(81.79,96.36) 82.28,96.85 82.68,96.85 82.81,96.72 82.81,96.21 81.79,95.2 74.04,95.2 73.79,95.45 73.79,96.34 74.04,96.59 74.3,96.59 74.55,96.34 74.55,95.96 74.68,95.83 75.06,95.83 75.19,95.96 v1(75.19,96.47)
PS_MIO29_501_USB0_DIR: length 24.9
  TOP w0.102: U15.31 83.84,101.02 v1(82.81,102.05) ; U4.D11 v2(66.47,102.43)
  L6_SIG w0.114: v1(82.81,102.05) 82.28,101.53 82.28,101.13 81.38,100.22 80.09,100.22 78.88,99.02 75.23,99.02 74.08,100.17 74.08,100.44 73.93,100.58 73.73,100.58 73.58,100.44 73.58,100.17 73.44,100.02 73.23,100.02 73.09,100.17 73.09,100.44 72.94,100.58 72.74,100.58 72.59,100.44 72.59,100.17 72.45,100.02 72.24,100.02 72.1,100.17 72.1,100.64 71.95,100.78 69.21,100.78 68.78,101.22 68.78,102.02 68.39,102.41 67.86,102.41 67.47,102.03 66.87,102.03 v2(66.47,102.43)
PS_MIO30_501_USB0_STP: length 25.2
  TOP w0.102: U4.B15 68.16,99.13 69.09,99.13 69.85,98.37 72.52,98.37 75.06,95.83 v1(75.95,95.83) ; v1(83.82,102.05) 84.2,102.05 84.84,101.42 U15.29
  L6_SIG w0.114: v1(75.95,95.83) 76.33,95.83 76.58,95.58 80.14,95.58 81.28,96.72 81.28,97.74 81.79,98.24 82.55,98.24 83.82,99.51 v1(83.82,102.05)
PS_MIO31_501_USB0_NXT: length 24
  TOP w0.102: U15.2 81.94,98.86 v1(81.41,99.39) ; U4.C12 v2(67.27,101.63)
  L6_SIG w0.114: v1(81.41,99.39) 80.9,99.9 80.26,99.9 78.99,98.63 73.57,98.63 73.42,98.77 73.42,99.37 73.28,99.51 73.07,99.51 72.93,99.37 72.93,98.77 72.78,98.63 72.58,98.63 72.43,98.77 72.43,99.37 72.29,99.51 72.08,99.51 71.94,99.37 71.94,98.77 71.79,98.63 71.59,98.63 71.44,98.77 71.44,99.37 71.3,99.51 71.09,99.51 70.95,99.37 70.95,98.77 70.8,98.63 70.6,98.63 70.45,98.77 70.45,99.37 70.31,99.51 69.58,99.51 68.47,100.63 68.47,101.93 68.27,102.13 67.97,102.13 67.47,101.63 v2(67.27,101.63)
PS_MIO32_501_USB0_D0: length 22.8
  TOP w0.102: v1(73.28,95.32) 71.76,96.85 69.09,96.85 68.84,97.1 66.93,97.1 65.27,98.77 U4.E15 ; U15.3 80.75,98.36 80.52,98.59 v1(80.52,99.35)
  L6_SIG w0.114: v1(73.28,95.32) 73.28,96.34 74.3,97.35 75.42,97.35 76.18,98.12 79.29,98.12 v1(80.52,99.35)
PS_MIO33_501_USB0_D1: length 22.1
  TOP w0.102: v1(78.68,99.72) 80.54,97.86 U15.4 ; v2(67.27,102.42) 67.28,102.42 U4.C11
  L6_SIG w0.114: v1(78.68,99.72) 77.58,99.72 77.43,99.87 77.43,100.64 77.29,100.78 77.08,100.78 76.94,100.64 76.94,99.87 76.79,99.72 76.59,99.72 76.44,99.87 76.44,100.64 76.3,100.78 76.09,100.78 75.95,100.64 75.95,99.87 75.8,99.72 75.49,99.72 74.29,100.92 72.48,100.92 72.28,101.12 69.48,101.12 69.08,101.52 69.08,102.22 68.48,102.82 67.87,102.82 67.67,102.62 v2(67.27,102.42)
PS_MIO34_501_USB0_D2: length 25.3
  TOP w0.102: v1(81.79,97.36) U15.5 ; U4.D15 66.07,98.75 66.83,97.99 68.71,97.99 69.47,97.23 72.14,97.23 73.92,95.45 v1(73.92,94.31)
  L6_SIG w0.114: v1(81.79,97.36) 82.93,97.36 83.24,97.05 83.24,95.12 82.93,94.82 74.43,94.82 v1(73.92,94.31)
PS_MIO35_501_USB0_D3: length 23.7
  TOP w0.102: v1(77.35,96.97) 76.84,97.48 74.93,97.48 72.9,99.51 70.23,99.51 69.32,100.43 U4.A14 ; U15.6 80.26,96.86 v1(79.76,97.36)
  L6_SIG w0.114: v1(77.35,96.97) 76.84,96.97 76.58,97.23 76.58,97.61 76.71,97.74 77.85,97.74 77.98,97.61 77.98,96.72 78.11,96.59 78.48,96.59 78.62,96.74 78.62,97.59 78.77,97.74 78.97,97.74 79.12,97.59 79.12,96.74 79.26,96.59 80.01,96.59 80.52,97.1 80.52,97.71 80.37,97.86 79.89,97.86 79.76,97.74 v1(79.76,97.36)
PS_MIO36_501_USB0_CLK: length 23.1
  TOP w0.102: U15.1 v1(82.64,100.02) ; U4.B14 68.08,100.02 69.22,100.02 70.11,99.13 72.77,99.13 74.81,97.1 75.19,97.1 75.31,96.97 v1(75.95,96.97)
  L6_SIG w0.114: v1(82.64,100.02) 82.64,100.4 82.77,100.53 83.32,100.53 83.44,100.4 83.44,99.64 82.43,98.63 81.16,98.63 80.9,98.37 80.9,96.97 79.89,95.96 79.04,95.96 78.78,96.21 78.54,96.21 78.29,95.96 78.04,95.96 77.79,96.21 77.55,96.21 77.3,95.96 76.97,95.96 v1(75.95,96.97)
PS_MIO37_501_USB0_D5: length 24.4
  TOP w0.102: U15.9 83.34,94.59 83.06,94.31 v1(82.68,94.31) ; U4.C14 67.24,100.06 67.24,99.21 67.69,98.75 68.96,98.75 69.73,97.99 72.39,97.99 74.93,95.45 v1(74.93,94.31)
  L6_SIG w0.114: v1(74.93,94.31) 75.44,94.31 76.08,93.67 78.62,93.67 78.76,93.82 78.76,94.16 78.91,94.31 79.11,94.31 79.26,94.16 79.26,93.82 79.4,93.67 79.61,93.67 79.75,93.82 79.75,94.16 79.9,94.31 80.1,94.31 80.25,94.16 80.25,93.82 80.39,93.67 80.6,93.67 80.74,93.82 80.74,94.16 80.89,94.31 81.09,94.31 81.24,94.16 81.24,93.82 81.38,93.67 81.59,93.67 81.73,93.82 81.73,94.16 81.88,94.31 v1(82.68,94.31)
PS_MIO38_501_USB0_D6: length 25.5
  TOP w0.102: v1(82.68,93.29) 83.84,94.45 U15.10 ; U4.A13 68.87,100.83 69.43,100.83 70.36,99.9 73.16,99.9 v1(75.06,97.99)
  L6_SIG w0.114: v1(75.06,97.99) 74.43,97.99 72.77,96.34 72.77,94.43 73.41,93.8 75.19,93.8 75.7,93.29 v1(82.68,93.29)
PS_MIO39_501_USB0_D7: length 25.5
  TOP w0.102: U15.13 85.34,94.41 v1(85.12,94.18) ; U4.D14 66.5,100 66.5,98.88 67.01,98.37 68.84,98.37 69.6,97.61 72.27,97.61 74.43,95.45 74.43,93.8 v1(74.93,93.29)
  L6_SIG w0.114: v1(85.12,94.18) 83.72,92.78 75.44,92.78 v1(74.93,93.29)
PWR_CLK: length 39.1
  TOP w0.127: U3.1 100.2,94.43 v1(100.97,95.2) R5.2
  L6_SIG w0.203: v1(100.97,95.2) 100.97,96.9 100.47,97.39 100.47,101.08 101.24,101.84 101.24,111.11 100.6,111.74 98.44,111.74 96.92,113.27 89.35,113.27 v1(88.31,114.31)
  BOTTOM w0.203: R89.2 92.37,114.28 R90.1 v1(88.31,114.31)
RX1A_N: length 2.6
  TOP w0.229: U5.M2 arc(33.92,107.7) 33.72,107.76 33.53,107.76 arc(33.18,107.81) 32.87,107.97 32.38,108.33 arc(32.08,108.43) C133.2
RX1A_P: length 2.5
  TOP w0.229: U5.M1 arc(34.03,108.22) 33.89,108.16 33.53,108.16 arc(33.31,108.2) 33.11,108.3 32.41,108.81 arc(32.3,108.94) 32.25,109.11 arc(32.26,109.19) C134.2
SCL: length 21.9
  TOP w0.102: v2(58.07,97.93) 58.79,98.65 59.06,98.65 59.27,98.86 59.27,100.03 U4.M14
  TOP w0.127: v1(65.03,86.31) 65.03,87.02 R79.2 65.2,87.08 U11.2
  BOTTOM w0.127: v1(65.03,86.31) 64.39,86.31 64.14,86.05 63,86.05 59.06,89.99 59.06,95.32 58.68,95.7 58.68,97.32 58.07,97.93 v2(58.07,97.93)
SDA: length 24.3
  TOP w0.102: v2(58.07,98.73) 58.47,99.13 58.47,100.03 U4.N14
  TOP w0.127: U11.3 65.91,86.43 65.66,86.18 65.66,86 R78.2 65.03,85.37 v1(65.03,84.66)
  BOTTOM w0.127: v2(58.07,98.73) 59.06,97.74 59.06,95.83 59.44,95.45 59.44,90.12 63.12,86.43 64.01,86.43 64.39,86.81 65.28,86.81 65.66,86.43 65.66,85.29 v1(65.03,84.66)
SYNC: length 7.1
  TOP w0.305: U3.10 U3.11 98.65,89.73 ; U3.10 U3.9 ; U3.10 98,89.73 ; U3.9 97.35,89.73 ; U3.9 96.91,90.48
  TOP w1.524: 97.98,85.93 L4.1 96.99,88.02
TX1A_N: length 3.8
  TOP w0.229: L8.2 31.19,101.71 arc(31.45,101.89) 31.76,101.95 32.1,101.95 arc(32.42,102.01) 32.7,102.2 33.33,102.83 arc(33.48,102.93) 33.65,102.96 33.77,102.96 arc(33.87,102.94) 33.96,102.88 U5.M8
TX1A_P: length 3.8
  TOP w0.229: U5.M7 33.98,103.45 arc(33.89,103.39) 33.77,103.37 33.65,103.37 arc(33.32,103.3) 33.04,103.12 32.41,102.49 arc(32.27,102.39) 32.1,102.36 31.76,102.36 arc(31.45,102.42) 31.18,102.6 L9.2
TX_VCO_1P1V_SUPPLY: length 3.4
  TOP w0.305: U5.A11 v2(43.28,99.96) ; U5.B11 v2(42.48,99.96)
  BOTTOM w0.305: v2(43.28,99.96) 43.7,99.96 C128.1 R52.1
  BOTTOM w0.406: v2(42.48,99.96) v2(43.28,99.96)
UART_RX: length 48.8
  TOP w0.127: P1.1 71.38,76.91 70.62,76.15 69.47,76.15 RX.1 ; U4.C6 v2(66.47,107.23)
  L5_SIG w0.127: v1(73.41,83) 74.05,83.64 74.68,83.64 76.33,85.29 76.33,93.83 74.04,96.12 74.04,98.24 75.06,99.26 75.06,101.93 73.41,103.58 69.47,103.58 67.82,105.23 65.47,105.23 65.27,105.43 65.27,107.43 65.47,107.63 66.07,107.63 v2(66.47,107.23)
  BOTTOM w0.127: P1.1 70.49,78.94 70.49,80.07 v1(73.41,83)
UART_TX: length 47
  TOP w0.127: U4.B7 v2(68.07,105.63) ; 72.65,76.78 P1.3
  TOP w0.152: TX.1 72.65,76.78
  L5_SIG w0.127: v2(68.07,105.63) 68.07,105.63 69.49,104.21 73.92,104.21 76.46,101.67 76.46,100.4 76.84,100.02 76.84,85.29 v1(74.55,83)
  BOTTOM w0.127: P1.3 72.65,77.29 72.39,77.04 70.62,77.04 70.11,77.54 70.11,80.59 73.16,83.64 73.92,83.64 v1(74.55,83)
UNNAMED_2_ADM7160V2_I254_VIN: length 4.1
  TOP w0.305: 59,88 U12.6 59.68,87.59
  TOP w0.762: 61.34,88.21 E2.2 60.46,87.39 ; 59.5,88.53 C173.1 60.14,89.23
UNNAMED_2_ADP1754_I93_SS: length 1.5
  TOP w0.203: U1.7 31.62,84.09 C2.1
UNNAMED_2_ADP1754_I233_SS: length 1.5
  TOP w0.203: U7.7 53.21,84.09 C12.1
UNNAMED_2_ADP2164_I29_EN: length 13.4
  TOP w0.203: C13.1 98.29,96.34 98.81,96.34 99.32,96.85 99.71,96.85 R10.1 R5.1 101.11,97.09 102.24,95.96 102.24,92.78
  TOP w0.305: R1.1 101.98,92.49 ; R1.1 102.44,92.08 ; R1.1 101.53,92.08 ; C13.1 98,96.05 U3.3 ; 101.04,92.78 U3.15 U3.14 101.04,92.13
UNNAMED_2_ADP2164_I29_RT: length 3.4
  TOP w0.127: U3.2 v1(98.65,95.41) 98.94,95.7 99.56,95.7 R10.2
  BOTTOM w0.127: R3.2 99.42,95.41 v1(98.65,95.41)
UNNAMED_2_FERRITE_I303_N1: length 11.7
  BOTTOM w0.508: E3.1 47.57,131.96 49.15,133.55 49.15,135.84 VDD_GPO.1
UNNAMED_2_RES_I251_N2: length 2.3
  BOTTOM w0.305: R7.1 93.22,91.01 93.63,91.41 R4.2
UNNAMED_3_ICXC7Z010_I16_PSCLK50: length 7
  TOP w0.127: 68.96,106.25 68.78,106.43 67.27,106.43 U4.C7
  TOP w0.305: 68.96,106.25 70.11,106.25 70.49,106.63 R12.2
UNNAMED_3_ICXC7Z010_I16_PSMIO75: length 5
  TOP w0.127: U4.D9 v2(66.47,104.03)
  BOTTOM w0.127: v2(66.47,104.03) 66.91,104.47 67.57,104.47 67.69,104.34 70.29,104.34 R83.2
UNNAMED_3_ICXC7Z010_I16_PSMIO85: length 8.8
  TOP w0.127: R84.1 75.06,108.79 73.91,107.63 73.17,107.63 72.78,107.23 68.08,107.23 U4.B6
UNNAMED_3_RES_I2_N1: length 2.6
  TOP w0.305: Y2.1 78.86,108.02 R8.2 80.14,108.04 R9.1
UNNAMED_3_RES_I48_N1: length 2.5
  TOP w0.305: Y2.3 76.64,106.63 R12.1
UNNAMED_4_ICMT41K256M16_I98_ZQ: length 4.2
  TOP w0.127: U2.L8 61.36,121.35 v2(61.36,118.45)
  BOTTOM w0.165: v2(61.36,118.45) 61.36,117.74 R165.1
UNNAMED_4_ICTPS51206_I44_S3: length 1.8
  TOP w0.127: U14.7 44.89,125.31 v2(44.78,125.42)
  BOTTOM w0.127: R222.2 45.09,124.9 45.09,125.12 v2(44.78,125.42)
UNNAMED_4_ICTPS51206_I44_S5: length 3.7
  TOP w0.127: U14.9 43.8,124.51 v1(43.31,124.03)
  BOTTOM w0.127: v1(43.31,124.03) 43.69,124.41 44.09,124.41 R221.2
UNNAMED_4_ICTPS51206_I44_VLDOIN: length 2.6
  TOP w0.203: 48.4,124.51 U14.2
  TOP w0.508: 48.72,123.76 R44.2 ; R44.2 49.28,124.32 ; R44.2 49.84,123.76
UNNAMED_4_ICTPS51206_I44_VTTSNS: length 3
  TOP w0.203: v2(48.39,126.06) 48.05,125.71 U14.5
  BOTTOM w0.305: v2(48.39,126.06) 48.39,126.37 C80.1 49.74,126.76 R43.2
UNNAMED_4_ICXC7Z010_I26_PSDDR_1: length 3.4
  TOP w0.127: U4.H3 v2(63.27,109.63)
  BOTTOM w0.127: R40.1 62.87,111.64 62.87,110.03 v2(63.27,109.63)
UNNAMED_4_ICXC7Z010_I26_PSDDRVR: length 1.2
  TOP w0.127: U4.J3 v2(61.67,109.63)
  BOTTOM w0.127: v2(61.67,109.63) 61.76,109.54 R41.1
UNNAMED_5_CAP_I17_N1: length 24.1
  TOP w0.305: U4.F7 64.87,106.43 v2(64.87,106.43)
  L6_SIG w0.102: 66.07,105.07 66.07,105.83 65.87,106.04 65.27,106.04 65.27,105.09 65.29,105.07 64.73,105.07 64.47,105.33 U4.F7
  L6_SIG w0.305: 65.27,106.04 v2(64.87,106.43) U4.F7 ; 71.27,105.38 70.96,105.07 65.29,105.07
  L6_SIG w0.508: 71.27,105.38 73.3,107.41 74.05,107.41 75.38,108.73 75.38,111.44 v1(75.88,111.94)
  BOTTOM w0.305: C98.1 64.39,106.92 v2(64.87,106.43)
  BOTTOM w0.508: v1(75.88,111.94) 75.88,112.7 C93.1
  BOTTOM w0.635: E5.2 75.9,113.85 C93.1
UNNAMED_5_CAP_I17_N2: length 29
  TOP w0.305: U4.H7 62.47,106.43 v2(62.47,106.43) U4.J7 ; U4.G8 v2(64.07,105.63) U4.F8 ; U4.F6 v2(64.87,107.23)
  L6_SIG w0.305: 63.27,106.43 63.27,105.94 63.57,105.63 v2(64.07,105.63) 64.07,104.93 64.4,104.59 71.54,104.59 71.88,104.93 ; 63.27,106.43 v2(62.47,106.43) ; 63.27,106.43 64.06,107.23 v2(64.87,107.23)
  L6_SIG w0.508: 71.88,104.93 73.53,106.58 75.53,106.58 76.88,107.93 v1(76.88,111.94)
  BOTTOM w0.305: C98.2 64.65,107.55 64.87,107.34 v2(64.87,107.23)
  BOTTOM w0.508: v1(76.88,111.94) 76.88,112.71 C93.2
  BOTTOM w0.635: C93.2 E6.2
UNNAMED_5_DIOLED_I60_N: length 1.6
  TOP w0.127: R48.1 116.12,93.29 DS1.C
UNNAMED_5_DIOLED_I62_N: length 2.5
  TOP w0.127: R87.1 115.51,86.62 116.21,85.92 DS2.C
UNNAMED_5_ICXC7Z010_I13_DONE0: length 67.5
  TOP w0.127: Q1.1 110.93,91.69 v1(110.49,91.26) ; U4.M7 v2(59.27,106.43)
  L6_SIG w0.127: v1(110.49,91.26) 100.71,91.26 98.87,89.42 95.19,89.42 94.36,90.24 94.36,96.34 91.66,99.04 90.77,99.04 86.19,103.63 82.58,103.63 81.18,102.23 78.68,102.23 77.28,103.63 62.07,103.63 61.27,104.43 61.27,106.63 61.07,106.83 59.67,106.83 v2(59.27,106.43)
UNNAMED_5_ICXC7Z010_I13_INITB0: length 8.3
  TOP w0.127: v1(70.77,108.73) 72.96,108.73 R47.1 ; U4.D5 v2(66.47,108.03)
  L5_SIG w0.127: v1(70.77,108.73) 69.87,108.73 69.17,108.03 v2(66.47,108.03)
UNNAMED_5_ICXC7Z010_I13_PROGRAM: length 4
  TOP w0.127: U4.K6 v2(60.87,107.23)
  BOTTOM w0.127: R46.1 59.67,105.32 59.67,106.83 60.07,107.23 60.87,107.23 v2(60.87,107.23)
UNNAMED_5_ICXC7Z010_I13_VCCBATT: length 5.2
  TOP w0.127: U4.E6 v2(65.67,107.23)
  BOTTOM w0.127: R45.2 68.47,104.93 68.47,105.83 68.28,106.03 66.27,106.03 66.07,106.23 66.07,106.83 v2(65.67,107.23)
UNNAMED_5_ICXC7Z010_I13_VP0: length 20
  TOP w0.127: v2(64.07,106.43) 63.67,106.03 U4.G7
  L6_SIG w0.127: v2(64.07,106.43) 64.47,106.83 66.77,106.83 67.47,106.13 70.18,106.13 71.03,106.98 71.93,106.98 72.98,108.03 73.88,108.03 74.88,109.03 74.88,111.74 75.08,111.94 v1(75.08,112.74)
  BOTTOM w0.127: R91.1 R11.2 75.28,111.33 75.28,111.94 75.08,112.14 v1(75.08,112.74)
UNNAMED_5_RES_I61_N2: length 2.7
  TOP w0.127: R48.2 113.92,93.05 113.92,90.92 Q1.3
UNNAMED_5_RES_I63_N2: length 2.6
  TOP w0.127: R87.2 114.09,86.47 Q4.3
UNNAMED_7_AD9363_I13_RBIAS: length 3.7
  TOP w0.178: 33.68,105.56 34.48,105.56
  TOP w0.305: 34.48,105.56 U5.L4
  TOP w0.406: 33.68,105.56 33.32,105.56 arc(32.68,105.69) 32.14,106.05 R49.2
UNNAMED_7_AD9363_I13_XTALN: length 4.5
  TOP w0.203: U5.M12 33.47,98.94 C124.1 33.47,95.45 C123.2
UNNAMED_7_CAP_I22_N2: length 1
  BOTTOM w0.305: C126.2 R51.1
UNNAMED_7_CAP_I30_N1: length 1
  BOTTOM w0.305: R52.2 44.69,98.26 C127.1
UNNAMED_7_CAP_I39_N2: length 2.2
  TOP w0.483: T5.4 arc(27.66,103.19) C132.2
UNNAMED_7_CAP_I40_N2: length 2.2
  TOP w0.483: T5.6 arc(27.66,101.11) C131.2
UNNAMED_7_CAP_I51_N1: length 2.2
  TOP w0.483: T1.4 31.52,110.14 arc(31.69,109.89) C134.1
UNNAMED_7_CAP_I52_N1: length 2.2
  TOP w0.483: C133.1 31.22,108.64 30.72,108.64 arc(29.92,108.74) T1.6
UNNAMED_7_CAP_I53_N1: length 2.8
  TOP w0.203: C123.1 33.53,92.02 Y3.3
UNNAMED_7_CNBNC5P_I57_CNTR: length 17.8
  TOP w0.483: RX1A.1 17.27,118.27 arc(18.21,118.15) 19.09,117.78 20.84,116.77 T1.3
UNNAMED_7_CNBNC5P_I58_CNTR: length 18
  TOP w0.483: T5.3 22.02,103.42 arc(19.84,102.52) 18.95,100.35 18.95,97.88 arc(18.75,96.91) 18.21,96.09 17.62,95.51 arc(16.87,95) 15.98,94.83 TX1A.1
UNNAMED_9_ADM1177_I23_GATE: length 1.9
  TOP w0.203: Q3.1 94.95,132.84 v1(94.14,132.03)
  BOTTOM w0.203: U10.10 v1(94.14,132.03)
UNNAMED_9_ADM1177_I23_ON: length 3
  BOTTOM w0.203: R71.2 100.23,130.43 U10.3
  BOTTOM w0.254: R72.1 R71.2
UNNAMED_9_ADM1177_I23_SENSE: length 5.6
  TOP w0.762: Q3.3 98.34,131.9 ; Q3.3 97.39,131.14 ; Q3.3 97.39,132.66
  TOP w1.016: 98.86,134.44 R73.2 99.76,133.49
  BOTTOM w0.203: v1(97.3,130.79) 97.44,130.93 U10.2
UNNAMED_9_ADM1177_I23_SS: length 1.9
  BOTTOM w0.305: U10.9 93.01,130.93 C155.1
UNNAMED_9_ADM1177_I23_TIMER: length 1.6
  BOTTOM w0.203: C156.1 98.48,127.92 U10.5
UNNAMED_9_ADM1177_I23_VCC: length 8.6
  TOP w1.016: 102.57,134.44 R73.1 101.67,133.49
  TOP w1.27: 103.31,131.02 D3.C 102.11,132.41
  BOTTOM w0.203: v1(101.6,132.92) 100.97,132.92 100.37,132.32 R71.1 100.24,131.43 U10.1
UNNAMED_9_ADP198_I329_VOUT: length 8.2
  TOP w0.254: 112.4,115.27 U16.A2 112.01,114.88
  TOP w0.635: C171.1 112.34,114.56 ; C171.1 112.97,113.87 ; C171.1 112.34,113.17 ; C172.1 112.34,112.79 ; C172.1 112.97,112.09 ; C172.1 112.34,111.39
  BOTTOM w0.508: 111.75,109.57 F1.1 ; F1.1 111.75,110.79 ; F1.1 112.28,110.18 ; 112.25,111.53 R88.1 ; R88.1 112.25,112.65 ; R88.1 112.78,112.09
  vias: v1(112.14,112.98) v1(112.14,111.2) v1(112.91,112.98) v1(112.91,111.2)
UNNAMED_9_ADP2114_I196_EN1: length 4.1
  TOP w0.127: U6.28 v2(100.34,112.6)
  BOTTOM w0.203: v2(100.34,112.6) 99.56,111.82 R85.2 R86.2
UNNAMED_9_ADP2114_I196_FREQ: length 1.6
  TOP w0.305: U6.3 104.63,115.4 R53.2
UNNAMED_9_ADP2114_I196_OPCFG: length 1.8
  TOP w0.305: U6.6 103.77,116.9 v1(103.89,116.79)
  BOTTOM w0.508: v1(103.89,116.79) 103.01,116.79 R54.1
UNNAMED_9_ADP2114_I196_SS1: length 2.1
  TOP w0.203: v2(101.6,112.6) 101.34,112.98 U6.30
  BOTTOM w0.254: v2(101.6,112.6) 101.92,112.28 C7.2
UNNAMED_9_ADP2114_I196_SS2: length 1.9
  TOP w0.203: U6.11 101.34,119.33 v2(101.6,119.71)
  BOTTOM w0.305: v2(101.6,119.71) 101.6,119.19 C139.2
UNNAMED_9_ADP2114_I196_SW1: length 3.1
  TOP w0.305: 97.79,113.87 98.05,114.12 98.05,114.31 U6.24 97.44,114.4 ; 97.44,114.9 U6.23
  BOTTOM w0.203: R89.1 v1(95.78,114.28)
UNNAMED_9_ADP2114_I196_SW3: length 2.1
  TOP w0.305: 97.44,117.4 U6.18 ; 97.82,118.42 98.02,118.22 98.02,118.02 U6.17 97.44,117.9
UNNAMED_9_CAP_I163_N1: length 7.2
  TOP w0.762: 93.16,110.6 C146.1 92.26,109.55 ; 91.25,113.1 L3.2 92.24,111.01
  TOP w1.016: 91.66,109.26 L5.1 90.3,110.03
UNNAMED_9_CAP_I214_N2: length 1
  BOTTOM w0.508: R60.2 C147.2
UNNAMED_9_CAP_I224_N2: length 1
  TOP w0.305: R61.2 C144.2
UNNAMED_9_CHOKE4P_I327_N2: length 6.9
  TOP w0.102: 111.07,106.74 D1.C 110.93,106.74 ; 111.07,106.74 110.93,106.74 ; 111.07,106.74 112.54,106.74 112.73,106.55 P2.3 ; 110.93,106.74 108.7,106.74 108.21,106.25 108.21,105.86 108.48,105.59 L6.2
UNNAMED_9_CHOKE4P_I327_N3: length 7.2
  TOP w0.102: P2.2 112.72,107.2 112.53,107.01 109.85,107.01 ; D2.C 109.86,107.02 109.85,107.01 ; 109.85,107.01 108.59,107.01 107.94,106.36 107.94,105.85 107.68,105.59 L6.3
UNNAMED_9_CN5P3SHLD_I255_N6: length 3.8
  TOP w0.635: 115.02,110.72 P2.SH3 116.23,111.49
  TOP w0.762: 115.96,112.79 R55.1 115,111.88
UNNAMED_9_CN5P3SHLD_I256_N6: length 4.1
  TOP w0.635: P3.SH1 114.75,120.15
  TOP w0.762: 113.75,118.95 R58.1 112.84,119.9 ; 116.23,119.39 P3.SH1
UNNAMED_9_ICNCP339_I277_EN: length 2.9
  TOP w0.203: U8.C2 110.94,124.22 110.51,123.78 R68.2 109.99,122.62 R69.1
UNNAMED_9_ICNCP339_I278_EN: length 6.7
  TOP w0.203: U9.C2 107.19,110.44 106.82,110.8 R70.2 106.68,111.45 107.7,112.47 107.7,113.61 v1(108.46,114.37)
  BOTTOM w0.203: Q2.3 108.46,115.24 v1(108.46,114.37)
